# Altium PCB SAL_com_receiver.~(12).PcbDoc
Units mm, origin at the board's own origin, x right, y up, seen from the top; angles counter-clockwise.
Board outline 70 x 80 mm, 2 copper layers (Top Layer, Bottom Layer); 23 components, 22 nets, 93 pads, 2 vias.
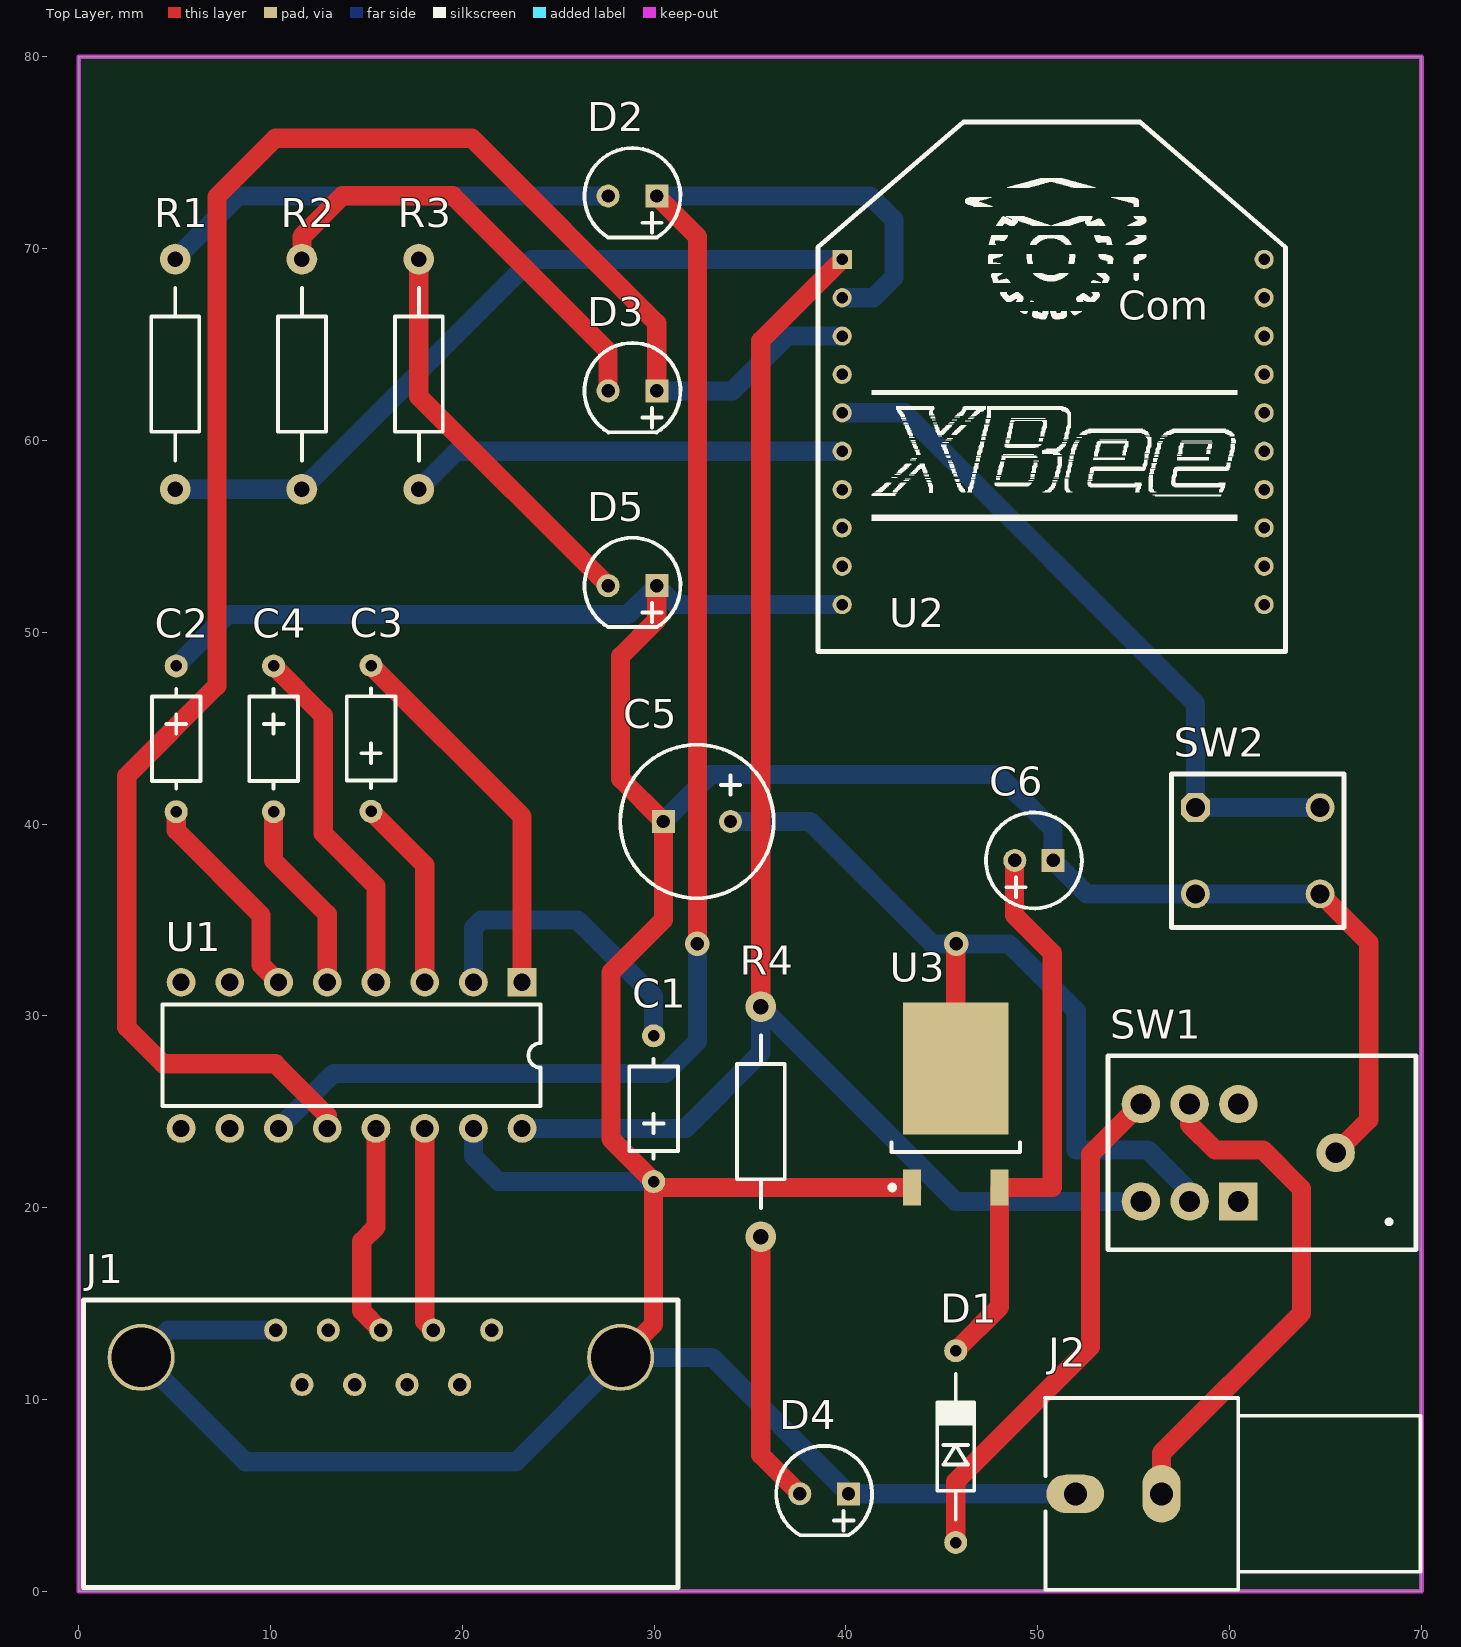
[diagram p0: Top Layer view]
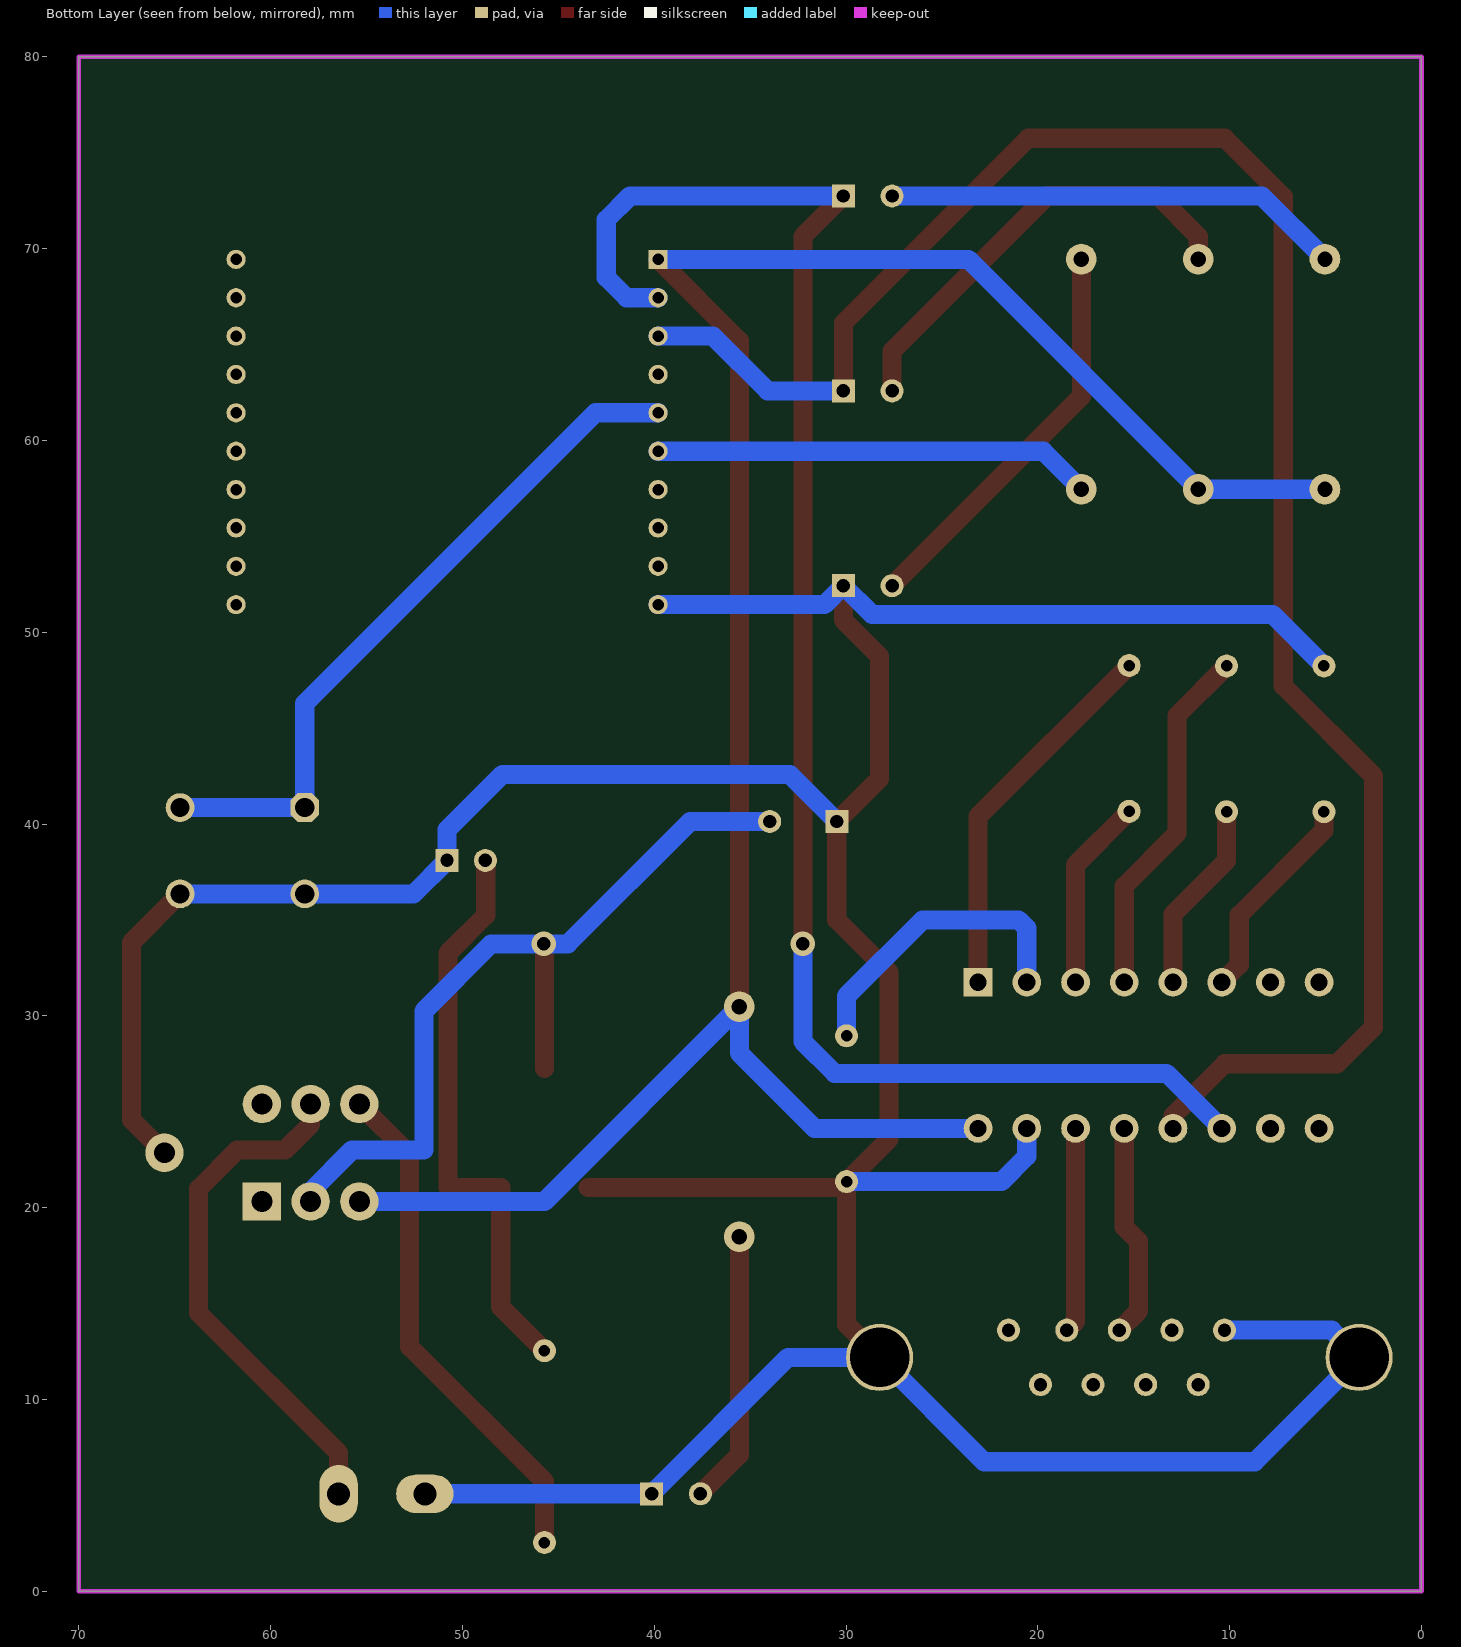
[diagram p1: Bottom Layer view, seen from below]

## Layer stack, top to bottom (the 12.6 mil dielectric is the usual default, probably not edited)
Top Layer: signal copper 0.0356
Dielectric: dielectric 0.32, FR-4, Dk 4.8
Bottom Layer: signal copper 0.0356

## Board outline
0,0 0,80 70,80 70,0

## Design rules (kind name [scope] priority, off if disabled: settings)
Clearance [All] p1: gap=0.254
PolygonConnect [All] p1: connectstyle=Relief reliefconductorwidth=0.254 reliefentries=4 polygonreliefangle="90 Angle"
RoomDefinition RoomDefinition_1 [All vs False] p1: confinementstyle=ConfineOut formatcopy=TRUE lockcomponents=FALSE outline 91,23.75 91.254,23.75 91.254,24.004 91,24.004
RoomDefinition SAL_com_receiver [InComponentClass('SAL_com_receiver')] p2: confinementstyle=ConfineIn formatcopy=TRUE lockcomponents=TRUE outline 0,0 70,0 70,80 0,80
RoutingVias [All] p1: holewidth=0.711 width=1.27 viastyle="Through Hole" minholewidth=0.711 minwidth=1.27 maxholewidth=0.711 maxwidth=1.27
SilkscreenOverComponentPads [All] p1: minsilkscreentomaskgap=0.254
SolderMaskExpansion [All] p1: expansion=0.102
TestPointUsage [All] p1: valid=0 allowmultiple=FALSE
Testpoint [All] p1: side=15 testpointundercomponent=TRUE minsize=1.016 maxsize=2.54 preferedsize=1.524 minholesize=0 maxholesize=1.016 preferedholesize=0.813 testpointgrid=0.025 style=1023 order=0-112345678
Width [All] p1: maxlimit=1 minlimit=0.254 preferedwidth=1
23 further rules are at their usual default settings.

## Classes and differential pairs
component class "Components Class 1": C1 C2 C3 C4 C5 C6 D1 D2 D3 D4 D5 R1 R2 R3 R4 SW1 SW2 U1 U2 U3 ""

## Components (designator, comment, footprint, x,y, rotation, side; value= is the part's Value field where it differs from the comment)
C1 "0.1 uF" "KEMET C410C104M5U5CA-TR" 29.972,28.956 r270 top
C2 "0.1 uF" "KEMET C410C104M5U5CA-TR" 5.08,40.64 r90 top
C3 "0.1 uF" "KEMET C410C104M5U5CA-TR" 15.24,48.26 r270 top
C4 "0.1 uF" "KEMET C410C104M5U5CA-TR" 10.16,40.64 r90 top
C5 "100 uF" "PANASONIC ECA1HAM101X" 30.48,40.132 r0 top
C6 "10 uF" "PANASONIC ECA1HAM100X" 50.8,38.1 r180 top
D1 "1N4148" "FAIRCHILD 1N4118" 45.72,2.54 r90 top
D2 "Yellow" "VISHAY TLLR4401" 27.598,72.742 r0 top
D3 "Red" "VISHAY TLLR4401" 27.598,62.582 r0 top
D4 "Green" "VISHAY TLLR4401" 37.592,5.08 r0 top
D5 "Blue" "VISHAY TLLR4401" 27.598,52.422 r0 top
J1 "DB9 Vertical" "TYCO 2-106505-2" 15.748,12.192 r0 top
J2 "RCA" RCA/4.5-H2 60.452,5.08 r0 top
R1 "1K" Resistência 5.03,57.452 r90 top
R2 "1K" Resistência 11.634,57.452 r90 top
R3 "1K" Resistência 17.73,57.452 r90 top
R4 "1K" Resistência 35.56,30.48 r270 top
SW1 "MULTICOMP 2AD1T2A2M7RE" "MULTICOMP 2AD1T2A2M7RE" 57.912,22.86 r90 top
SW2 "OMRON B3F-1002" "OMRON B3F-1002" 61.468,38.608 r180 top
U1 "MAX232ACPE" PE16A 14.224,27.94 r180 top
U2 "XBee" XBee 50.8,59.436 r0 top
U3 "LM1117DT-3.3" TD03B_N 45.72,25.4 r90 top
? "" "SAL_LOGO 2" 50.8,69.596 r0 top

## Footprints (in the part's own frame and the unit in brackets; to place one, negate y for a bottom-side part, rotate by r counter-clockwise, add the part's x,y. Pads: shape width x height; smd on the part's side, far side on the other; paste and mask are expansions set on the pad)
"FAIRCHILD 1N4118" [mm] "Diode"
  round 1.2 hole 0.6: A(0,0) K(10,0)
  silkscreen extent 1.2,-0.97 8.8,0.97
"KEMET C410C104M5U5CA-TR" [mm] "Axial Capacitor"
  round 1.2 hole 0.6: 1(0,0) 2(7.6,0)
  silkscreen extent 1.2,-1.27 6.4,1.27
"MULTICOMP 2AD1T2A2M7RE" [mm] "Switch, DPDT ON-ON"
  rect 2x2 hole 1.09: 1(-2.54,-2.54)
  round 2 hole 1.09: 2(-2.54,0) 3(-2.54,2.54) 4(2.54,-2.54) 5(2.54,0) 6(2.54,2.54) GND(0,-7.62)
  silkscreen extent -5.06,-11.81 5.06,4.25
"OMRON B3F-1002" [mm] "6.0mm Tactil Switch"
  oct 1.5x1.5 hole 1: 1(3.25,-2.25)
  round 1.5 hole 1: 2(-3.25,-2.25) 3(3.25,2.25) 4(-3.25,2.25)
  silkscreen extent -4.5,-4 4.5,4
"PANASONIC ECA1HAM100X" [mm]
  rect 1.2x1.2 hole 0.7: 1(0,0)
  round 1.2 hole 0.7: 2(2,0)
  silkscreen extent -1.5,-2.5 3.5,2.5
"PANASONIC ECA1HAM101X" [mm]
  rect 1.2x1.2 hole 0.7: 1(0,0)
  round 1.2 hole 0.7: 2(3.5,0)
  silkscreen extent -2.25,-4 5.75,4
PE16A [mm] "DIP; 16 Leads; Row Spacing 7.62 mm; Pitch 2.54 mm"
  rect 1.5x1.5 hole 0.9: 1(-8.89,-3.81)
  round 1.5 hole 0.9: 2(-6.35,-3.81) 3(-3.81,-3.81) 4(-1.27,-3.81) 5(1.27,-3.81) 6(3.81,-3.81) 7(6.35,-3.81) 8(8.89,-3.81) 9(8.89,3.81) 10(6.35,3.81) 11(3.81,3.81) 12(1.27,3.81) 13(-1.27,3.81) 14(-3.81,3.81) 15(-6.35,3.81) 16(-8.89,3.81)
  silkscreen extent -9.85,-2.65 9.85,2.65
RCA/4.5-H2 [mm] "Two Conductor Jack (RCA), Right Angle, Thru-Hole, Body 10 x 10 x 13 mm (WxTxH)"
  oval 2x3 hole 1.2: 1A(-4,0)
  oval 3x2 hole 1.2: 2B(-8.496,0)
  silkscreen extent -10.07,-5 9.5,5
Resistência [mm]
  round 1.6 hole 0.8: 1(0,0) 2(12,0)
  silkscreen extent 1.5,-1.25 10.5,1.25
"SAL_LOGO 2" [mm]
  silkscreen extent -4.6,-3.28 4.88,4.19
TD03B_N [mm] "D-PAK, 4-Leads, Body 6.1x6.6mm, Pitch 2.29mm, Lead Span 9.7mm, IPC Medium Density"
  rect 1.9x0.95 smd: 1(-4.35,2.28) 3(-4.35,-2.28)
  rect 6.9x5.5 smd: 4(1.85,0)
  silkscreen extent -4.47,-3.35 -2,3.43
"TYCO 2-106505-2" [mm] "D-SUB 9WAY Right Angle"
  round 1.2 hole 0.7: 1(5.78,1.42) 2(2.74,1.42) 3(0,1.42) 4(-2.74,1.42) 5(-5.48,1.42) 6(4.11,-1.42) 7(1.37,-1.42) 8(-1.37,-1.42) 9(-4.11,-1.42)
  round 3.5 hole 3.1: 10(12.5,0) 11(-12.5,0)
  silkscreen extent -15.5,-12 15.5,3
"VISHAY TLLR4401" [mm] "3mm LED"
  round 1.2 hole 0.7: 1(0,0)
  rect 1.2x1.2 hole 0.7: 2(2.54,0)
  silkscreen extent -1.23,-2.17 3.77,2.5
XBee [mm] "ZigBee device"
  rect 1x1 hole 0.6: 1(-11,10)
  round 1 hole 0.6: 2(-11,8) 3(-11,6) 4(-11,4) 5(-11,2) 6(-11,0) 7(-11,-2) 8(-11,-4) 9(-11,-6) 10(-11,-8) 11(11,-8) 12(11,-6) 13(11,-4) 14(11,-2) 15(11,0) 16(11,2) 17(11,4) 18(11,6) 19(11,8) 20(11,10)
  silkscreen extent -12.26,-10.44 12.12,17.17

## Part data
C1 C2 C3 C4: library part "KEMET C410C104M5U5CA-TR", "0.1 uF axial capacitor 50V Z5U"
C5: library part "PANASONIC ECA1HAM101X"
C6: library part "PANASONIC ECA1HAM100X"
D1: library part "FAIRCHILD 1N4148", "Diode Switching 75V 500 MW DO-35"
D2 D3 D4 D5: library part "VISHAY TLLG4401", "Green LED PCB 3mm"
J1: library part "TYCO 2-106505-2"
J2: "RCA Phono Jack, Right Angle, Thru-Hole, Snap-In"
R1 R2 R3 R4: library part Resistência
SW2: "6.0mm Tact Switch"
U1: "+5V Powered, Multi-Channel RS-232 Driver/Receiver"
U3: "800mA Low-Dropout Linear Regulator"

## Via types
v1: diameter 1.27, hole 0.711, Top Layer to Bottom Layer, 2 vias

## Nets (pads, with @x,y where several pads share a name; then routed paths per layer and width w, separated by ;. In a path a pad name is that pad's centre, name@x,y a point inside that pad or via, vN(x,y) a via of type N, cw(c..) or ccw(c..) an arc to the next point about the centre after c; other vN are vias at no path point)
3.3V: R1.1 R2.1 R4.1 SW1.3 U1.16 U2.1 | length 121
  Top Layer w1: R4.1 35.56,65.196 U2.1
  Bottom Layer w1: R1.1 R2.1 23.618,69.436 U2.1 ; U1.16 31.633,24.13 35.56,28.057 R4.1 45.72,20.32 SW1.3
"3.3V OUT": C5.2 SW1.2 U3.4 | length 43.2
  Top Layer w1: U3.4 45.72,33.72 v1(45.75,33.75)
  Bottom Layer w1: C5.2 38.1,40.132 ; 38.118,40.132 44.5,33.75 v1(45.75,33.75) 48.5,33.75 52,30.25 52,23 55.75,23 57.912,20.838 SW1.2
DIN: D3.2 U1.12 U2.3 | length 100.8
  Top Layer w1: U1.12 12.954,24.796 10.25,27.5 4.405,27.5 2.5,29.405 2.5,42.5 7.2,47.2 7.2,72.7 10.25,75.75 20.5,75.75 30.138,66.112 D3.2
  Bottom Layer w1: D3.2 34.082,62.582 36.936,65.436 U2.3
DOUT: D2.2 U1.11 U2.2 | length 87.7
  Top Layer w1: D2.2 32.25,70.63 v1(32.25,33.75)
  Bottom Layer w1: U1.11 13.284,27 30.589,27 32.25,28.661 v1(32.25,33.75) ; D2.2 41.258,72.742 42.5,71.5 42.5,68.5 41.436,67.436 U2.2
GND: C1.2 C2.2 C5.1 C6.1 D4.2 D5.2 J1.5 J1.10 J1.11 J2.2B SW1.GND SW2.3 SW2.4 U1.15 U2.10 U3.1 | length 224.4
  Top Layer w1: J1.10 29.972,13.916 C1.2 ; D5.2 30.138,50.638 28.25,48.75 28.25,42.362 C5.1 30.48,35.003 27.75,32.273 27.75,23.578 30.278,21.05 U3.1 ; SW2.4 67.25,33.826 67.25,24.578 SW1.GND
  Bottom Layer w1: C2.2 7.757,50.917 28.633,50.917 D5.2 31.124,51.436 U2.10 ; J1.5 4.668,13.612 J1.11 8.69,6.75 22.806,6.75 J1.10 33.02,12.192 D4.2 J2.2B ; U1.15 20.574,22.676 21.894,21.356 C1.2 ; C5.1 32.934,42.586 47.914,42.586 50.8,39.7 C6.1 52.542,36.358 SW2.3 SW2.4
NetC1_1: C1.1 U1.2 | length 16.2
  Bottom Layer w1: U1.2@20.706,31.75 U1.2 20.574,34.574 21,35 26,35 29.972,31.028 C1.1
NetC2_1: C2.1 U1.6 | length 11.1
  Top Layer w1: C2.1 5.08,39.67 9.5,35.25 9.5,32.664 U1.6
NetC3_1: C3.1 U1.1 | length 19.8
  Top Layer w1: C3.1 23.114,40.386 U1.1
NetC3_2: C3.2 U1.3 | length 10.1
  Top Layer w1: C3.2 18.034,37.866 U1.3
NetC4_1: C4.1 U1.5 | length 10
  Top Layer w1: C4.1 10.16,38.09 12.954,35.296 U1.5
NetC4_2: C4.2 U1.4 | length 18.7
  Top Layer w1: C4.2 12.75,45.65 12.75,39.5 15.494,36.756 U1.4
NetC6_2: C6.2 D1.K U3.3 | length 30.1
  Top Layer w1: D1.K 48,14.82 U3.3@48,21.047 ; C6.2 48.78,38.08 48.78,35.245 50.75,33.275 50.75,21.047 U3.3@48,21.047 ; U3.3@48,21.047 U3.3 U3.3@48,21.047
NetD2_1: D2.1 R1.2 | length 23.9
  Bottom Layer w1: R1.2 8.32,72.742 D2.1
NetD3_1: D3.1 R2.2 | length 23.4
  Top Layer w1: R2.2 11.634,70.634 13.75,72.75 19.5,72.75 27.598,64.652 D3.1
NetD4_1: D4.1 R4.2 | length 14.2
  Top Layer w1: R4.2 35.56,7.112 D4.1
NetD5_1: D5.1 R3.2 | length 21.1
  Top Layer w1: R3.2 17.73,62.29 D5.1
NetJ2_1A: J2.1A SW1.5 | length 27.2
  Top Layer w1: J2.1A 56.452,7.202 63.75,14.5 63.75,20.987 61.737,23 59.25,23 57.912,24.338 SW1.5
RESET: SW2.1 SW2.2 U2.5 | length 36.6
  Bottom Layer w1: U2.5 43.064,61.436 58.218,46.282 SW2.1 SW2.2
RSSI: R3.1 U2.6 | length 22.9
  Bottom Layer w1: R3.1 19.714,59.436 U2.6
RX: J1.3 U1.13 | length 11.2
  Top Layer w1: U1.13 15.494,18.989 14.75,18.245 14.75,14.61 J1.3
TX: J1.2 U1.14 | length 10.7
  Top Layer w1: U1.14 18.034,14.066 J1.2
VIN: D1.A SW1.6 | length 26.9
  Top Layer w1: D1.A 45.72,5.72 52.75,12.75 52.75,22.778 SW1.6
pads on no net: J1.1 J1.4 J1.6 J1.7 J1.8 J1.9 SW1.1 SW1.4 U1.7 U1.8 U1.9 U1.10 U2.4 U2.7 U2.8 U2.9 U2.11 U2.12 U2.13 U2.14 U2.15 U2.16 U2.17 U2.18 U2.19 U2.20

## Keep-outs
Top Layer:
  the board outline again, w0.254
Keep-Out Layer:
  the board outline again, w0.254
